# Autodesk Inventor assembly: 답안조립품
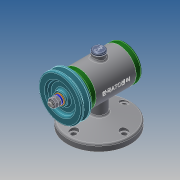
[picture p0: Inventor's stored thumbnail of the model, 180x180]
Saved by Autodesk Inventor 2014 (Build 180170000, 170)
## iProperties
Created: 2018-12
Part Number: 답안조립품
Document SubType Name: Assembly
Designer: 601-25
Author: 601-25
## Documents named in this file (15)
- C:\Users\601-25\Desktop\481208V1014\답안조립품.iam
- C:\Users\601-25\Desktop\481208V1014\본체.ipt
- C:\Users\601-25\Desktop\481208V1014\V벨트풀리.ipt
- C:\Users\601-25\Desktop\481208V1014\고무캡.ipt
- C:\Users\601-25\Desktop\481208V1014\너트 M8.ipt
- 너트 M8.ipt
- C:\Users\601-25\Desktop\481208V1014\뒤커버.ipt
- C:\Users\601-25\Desktop\481208V1014\베어링 15 x 32 x 9.ipt
- C:\Users\601-25\Desktop\481208V1014\볼트 M4 x 12.ipt
- C:\Users\601-25\Desktop\481208V1014\스프링와셔 8.ipt
- C:\Users\601-25\Desktop\481208V1014\앞커버.ipt
- C:\Users\601-25\Desktop\481208V1014\오일 실 15 25 7.ipt
- C:\Users\601-25\Desktop\481208V1014\와셔 8x17.ipt
- C:\Users\601-25\Desktop\481208V1014\축.ipt
- C:\Users\601-25\Desktop\481208V1014\키 3 x 3 x 12.ipt
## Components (2 placed, 2 different names)
1. V벨트풀리:1 — 각도:5
2. 고무캡:1 — 각도:2
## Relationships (2: Angle 2)
- 각도:2 [Angle]: 고무캡:1
- 각도:5 [Angle]: V벨트풀리:1
